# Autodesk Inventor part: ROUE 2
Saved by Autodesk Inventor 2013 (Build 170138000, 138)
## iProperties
Created: 2012-12
Part Number: ROUE 2
Material: Générique
Document SubType Name: Modeling
Designer: jost thierry
Density: 1 g/cm^3
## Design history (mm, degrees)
node "ROUE 21"
node "ROUE 2"
node "Base1"
